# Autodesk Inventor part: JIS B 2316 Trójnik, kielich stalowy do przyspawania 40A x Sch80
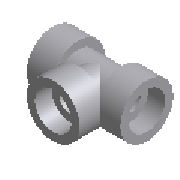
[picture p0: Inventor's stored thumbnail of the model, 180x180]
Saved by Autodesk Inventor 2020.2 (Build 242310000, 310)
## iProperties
Manager: www.cadconsulting.pl
Company: Fabian Stasiak CAD Consulting
IsCustomPart: 0
NAME: PIPING: JIS B 2316 Steel Socket Welding Tee
DATA: <meta><inlinegroups number="1" deflen="6.98"></inlinegroups><connections number="3"></connections><angles><a>3.14159265358979</a><a>1.57079632679489</a></angles
Created: 2014-02
Part Number: JIS B 2316 Trójnik, kielich stalowy do przyspawania 40A x Sch80
Material: Stal
Description: Trójnik
Document SubType Name: Modeling
Standard: JIS B 2316
Designer: F.Stasiak
Standards Organization: JIS
Language: pl-PL
Size Designation: 40A x Sch80
Categories: <MemberInstance><Categories><Category DisplayName="Rury cienko- i grubościenne" InternalName="4347fa0f-2144-441d-94cd-e3e15c92b736" Mnemonic="TUBEANDPIPE"><Cate
Density: 1 g/cm^3
Appearance: Płyta
Catalog Web Link: www.expertbooks.pl
Author: F.Stasiak
Subject: Zbiór ćwiczeń. Autodesk Inventor 2020. Kurs Professional
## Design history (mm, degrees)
sketch "Sketch1"
  geometry: L1 (0, 0)-(44.5, 0); L2 (44.5, 0)-(44.5, 26.2); L3 (18.3, 30.15)-(0, 30.15); L4 (0, 24.55)-(0, 0); L5 (12.7, 24.55)-(12.7, 20.6); L6 (12.7, 20.6)-(44.5, 20.6); L7 (18.3, 30.15)-(18.3, 26.2); L8 (18.3, 26.2)-(44.5, 26.2); L9 (0, 24.55)-(0, 30.15); L10 (76.3, 20.6)-(44.5, 20.6); L11 (89, 24.55)-(89, 30.15); L12 (70.7, 30.15)-(89, 30.15); L13 (70.7, 30.15)-(70.7, 26.2); L14 (70.7, 26.2)-(44.5, 26.2); L15 (89, 24.55)-(89, 0); L16 (89, 0)-(44.5, 0); L17 (0, 24.55)-(12.7, 24.55); L18 (89, 24.55)-(76.3, 24.55); L19 (76.3, 24.55)-(76.3, 20.6); L20 (0, 24.55)-(0, 0); L21 (0, 0)-(89, 0); L22 (89, 0)-(89, 24.55); C1 r 2.8 at (15.5, 27.35); C2 r 2.8 at (15.5, 23.4)
  constraints: 44 end point, 7 symmetric about line, 7 tangent, 5 perpendicular, 4 parallel, 2 centre point, 2 horizontal, 1 collinear, 1 equal radius, 1 point on line, 9 other
  dimensions: "d0" = 41.2 diameter of L6 L1 (= D); "d1" = 12.7 distance between parallel lines of L9 L5 (= C1); "d2" = 31.8 distance between parallel lines of L2 L5 (= G); "d6" = 49.1 diameter of L4.start L1 (= S); "d7" = 5.6 distance of L4.start L3.end (= T)
revolve "Revolve1" stored, may be unused: angle "d8" = 90 deg
sketch "Sketch2"
  geometry: L1 (0, 0)-(-44.5, 0) reference; L2 (-44.5, 0)-(-44.5, 44.5); L3 (-44.5, 44.5)-(-69.05, 44.5); L4 (-74.65, 44.5)-(-74.65, 26.2); L5 (-65.1, 0)-(-44.5, 0); L6 (-69.05, 31.8)-(-65.1, 31.8); L7 (-65.1, 31.8)-(-65.1, 0); L8 (-69.05, 44.5)-(-74.65, 44.5); L9 (-74.65, 26.2)-(-70.7, 26.2); L10 (-70.7, 26.2)-(-70.7, 0); L11 (-65.1, 0)-(-70.7, 0); L12 (-69.05, 44.5)-(-69.05, 31.8); L13 (-69.05, 44.5)-(-44.5, 44.5); L14 (-44.5, 44.5)-(-44.5, 0); L15 (-44.5, 0)-(-65.1, 0); C1 r 2.8 at (-71.85, 29); C2 r 2.8 at (-67.9, 29)
  constraints: 28 end point, 8 tangent, 6 perpendicular, 2 centre point, 2 parallel, 1 vertical
  dimensions: "d3" = 41.2 diameter of L7 L2 (= D); "d4" = 12.7 distance between parallel lines of L6 L8 (= C1); "d5" = 31.8 distance between parallel lines of L6 L5 (= G); "d9" = 49.1 diameter of L3.end L2 (= S); "d10" = 5.6 distance of L3.end L4.start (= T)
revolve "Revolve2" stored, may be unused: angle "d18" = 90 deg
revolve "Revolve3" stored, may be unused: angle "d57" = 90 deg
revolve "Revolve4" stored, may be unused: angle "d58" = 90 deg
workaxis "Work Axis1"
workaxis "Work Axis3"
workpoint "Work Point2"
workpoint "Work Point3"
workaxis "Work Axis4"
workpoint "Work Point4"
workpoint "Work Point5"
workaxis "Work Axis5"
workpoint "Work Point6"
workpoint "Work Point7"
body "Solid1"
other parameters: "S" = 49.1 [user parameter; used in 2 equation terms], "D" = 41.2 [user parameter; used in 2 equation terms], "T" = 5.6 [user parameter; used in 2 equation terms], "C1" = 12.7 [user parameter; used in 2 equation terms], "G" = 31.8 [user parameter; used in 2 equation terms], "Size_Designation" = 12.345 [user parameter]
